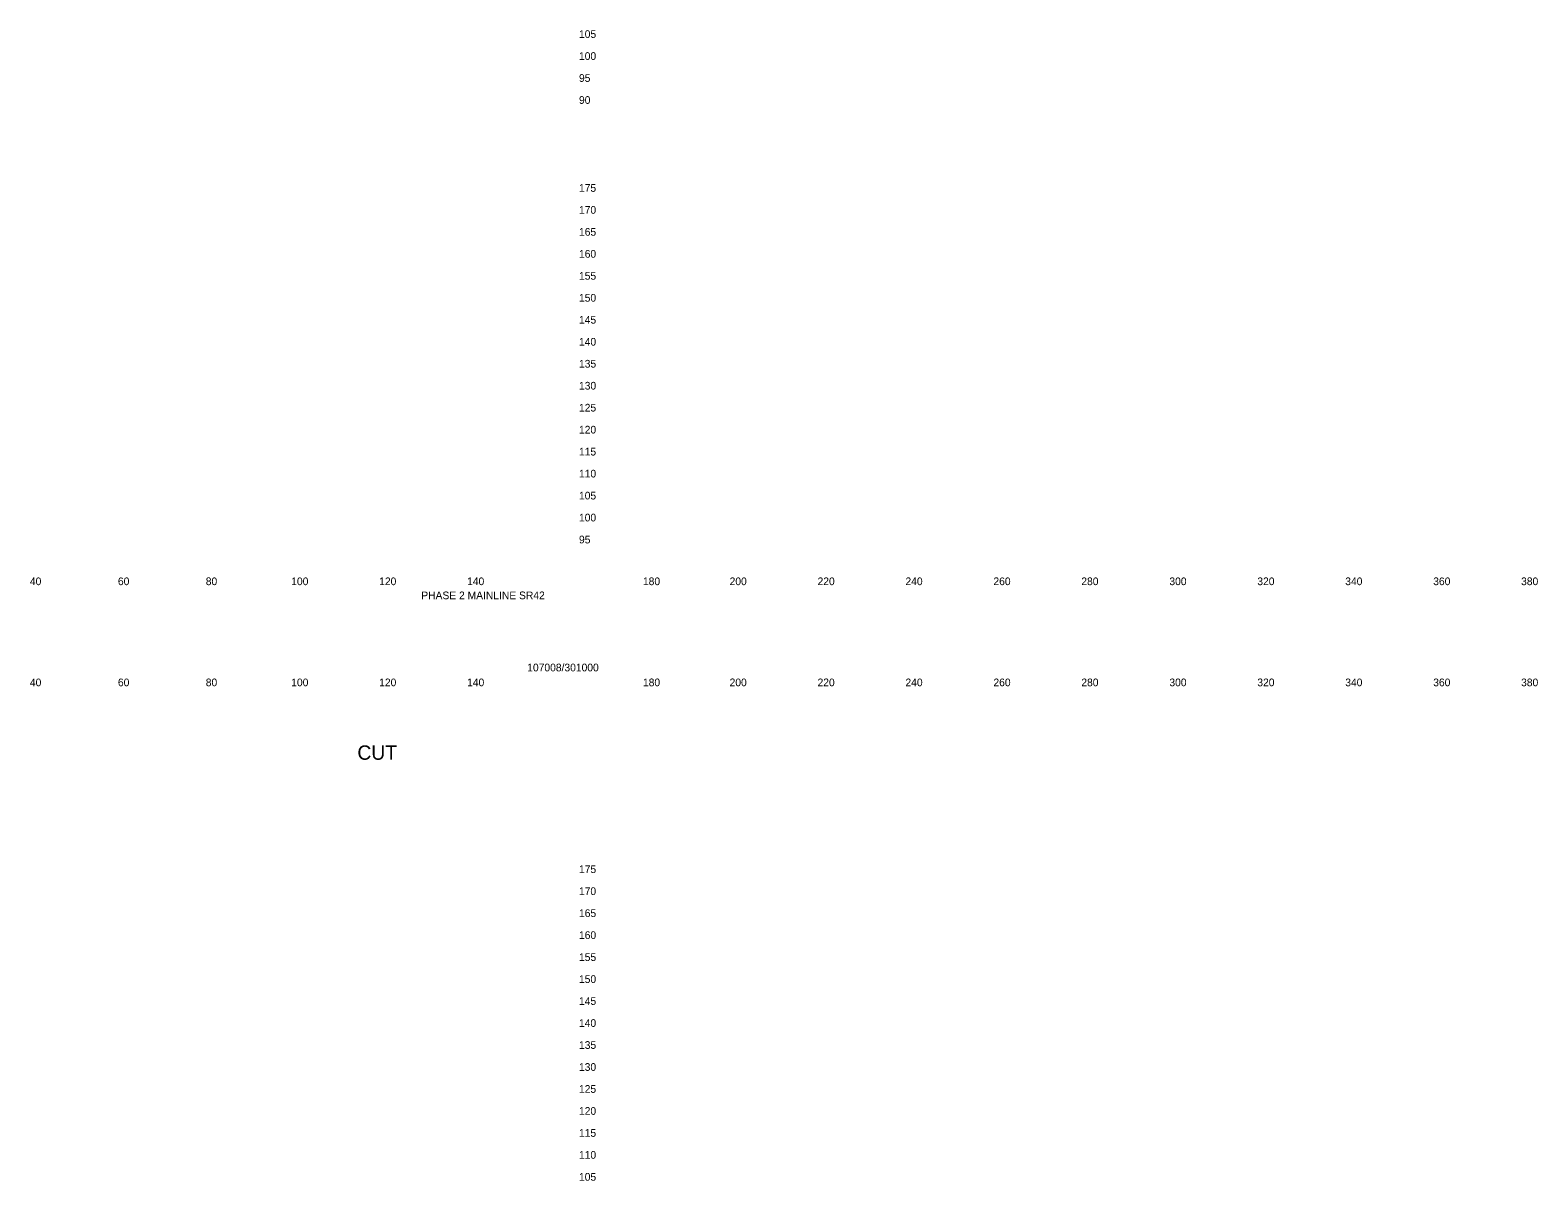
# Model space of a CAD drawing. Extents: x 21281 to 22024, y 6472 to 15208.
# Drawn here: x 21681.3 to 22024.2, y 11399.8 to 11661.6 of the extents above; entities that cross this region are included whole.
import ezdxf

# ---------------------------------------------------------------- set-up
doc = ezdxf.new("R2010")
doc.units = 0
doc.layers.add('XS_SHEET_LABELS_ELEVATION', color=7, linetype='Continuous')
doc.layers.add('XS_SHEET_LABELS_OFFSET', color=7, linetype='Continuous')

msp = doc.modelspace()

# ---------------------------------------------------------------- texts
at = {"layer": 'XS_SHEET_LABELS_ELEVATION'}
for s, p in [('  105  ', (21804.84, 11659.84)), ('  100  ', (21804.84, 11654.84)), ('  95  ', (21804.84, 11649.84)), ('  90  ', (21804.84, 11644.84)), ('  175  ', (21804.84, 11624.84)), ('  170  ', (21804.84, 11619.84)), ('  165  ', (21804.84, 11614.84)), ('  160  ', (21804.84, 11609.84)), ('  155  ', (21804.84, 11604.84)), ('  150  ', (21804.84, 11599.84)), ('  145  ', (21804.84, 11594.84)), ('  140  ', (21804.84, 11589.84)), ('  135  ', (21804.84, 11584.84)), ('  130  ', (21804.84, 11579.84)), ('  125  ', (21804.84, 11574.84)), ('  120  ', (21804.84, 11569.84)), ('  115  ', (21804.84, 11564.84)), ('  110  ', (21804.84, 11559.84)), ('  105  ', (21804.84, 11554.84)), ('  100  ', (21804.84, 11549.84)), ('  95  ', (21804.84, 11544.84)), ('  175  ', (21804.84, 11469.84)), ('  170  ', (21804.84, 11464.84)), ('  165  ', (21804.84, 11459.84)), ('  160  ', (21804.84, 11454.84)), ('  155  ', (21804.84, 11449.84)), ('  150  ', (21804.84, 11444.84)), ('  145  ', (21804.84, 11439.84)), ('  140  ', (21804.84, 11434.84)), ('  135  ', (21804.84, 11429.84)), ('  130  ', (21804.84, 11424.84)), ('  125  ', (21804.84, 11419.84)), ('  120  ', (21804.84, 11414.84)), ('  115  ', (21804.84, 11409.84)), ('  110  ', (21804.84, 11404.84)), ('  105  ', (21804.84, 11399.84))]:
    msp.add_text(s, height=1.75, dxfattribs=at).set_placement(p)
at = {"layer": 'XS_SHEET_LABELS_OFFSET'}
for s, height, p in [('  40  ', 1.75, (21679.95, 11535.34)), ('  60  ', 1.75, (21699.97, 11535.34)), ('  80  ', 1.75, (21719.95, 11535.34)), ('  100  ', 1.75, (21739.39, 11535.34)), ('  120  ', 1.75, (21759.39, 11535.34)), ('  140  ', 1.75, (21779.39, 11535.34)), ('  180  ', 1.75, (21819.39, 11535.34)), ('  200  ', 1.75, (21839.1, 11535.34)), ('  220  ', 1.75, (21859.1, 11535.34)), ('  240  ', 1.75, (21879.1, 11535.34)), ('  260  ', 1.75, (21899.11, 11535.34)), ('  280  ', 1.75, (21919.1, 11535.34)), ('  300  ', 1.75, (21939.13, 11535.34)), ('  320  ', 1.75, (21959.13, 11535.34)), ('  340  ', 1.75, (21979.13, 11535.34)), ('  360  ', 1.75, (21999.14, 11535.34)), ('  380  ', 1.75, (22019.13, 11535.34)), ('PHASE 2 MAINLINE SR42', 1.75, (21770.27, 11532.14)), ('107008/301000', 1.75, (21794.37, 11515.73)), ('  40  ', 1.75, (21679.95, 11512.34)), ('  60  ', 1.75, (21699.97, 11512.34)), ('  80  ', 1.75, (21719.95, 11512.34)), ('  100  ', 1.75, (21739.39, 11512.34)), ('  120  ', 1.75, (21759.39, 11512.34)), ('  140  ', 1.75, (21779.39, 11512.34)), ('  180  ', 1.75, (21819.39, 11512.34)), ('  200  ', 1.75, (21839.1, 11512.34)), ('  220  ', 1.75, (21859.1, 11512.34)), ('  240  ', 1.75, (21879.1, 11512.34)), ('  260  ', 1.75, (21899.11, 11512.34)), ('  280  ', 1.75, (21919.1, 11512.34)), ('  300  ', 1.75, (21939.13, 11512.34)), ('  320  ', 1.75, (21959.13, 11512.34)), ('  340  ', 1.75, (21979.13, 11512.34)), ('  360  ', 1.75, (21999.14, 11512.34)), ('  380  ', 1.75, (22019.13, 11512.34)), ('CUT', 3.273, (21755.74, 11495.61))]:
    msp.add_text(s, height=height, dxfattribs=at).set_placement(p)

doc.saveas('drawing.dxf')
